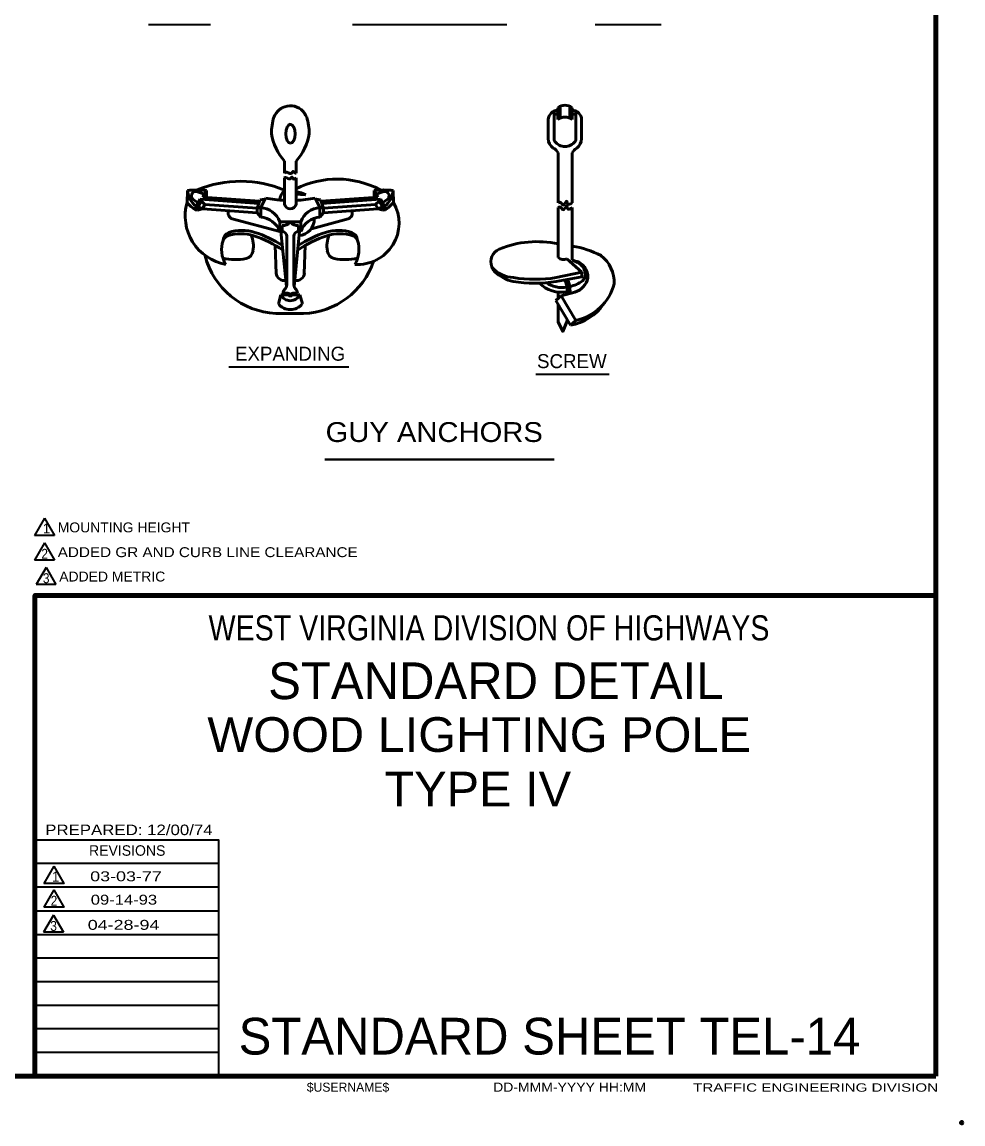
# Model space of a CAD drawing. Extents: x -34 to 821, y -14 to 530.
# Drawn here: x 593.8 to 821.5, y -13.8 to 252.8 of the extents above; entities that cross this region are included whole.
import ezdxf
from ezdxf.enums import TextEntityAlignment as Align

# ---------------------------------------------------------------- set-up
doc = ezdxf.new("R2010")
doc.units = 0
doc.header["$LTSCALE"] = 1.2
doc.header["$PDMODE"] = 32
doc.header["$PDSIZE"] = 0.6
doc.layers.add('1', color=7, linetype='Continuous', lineweight=53)
doc.layers.add('61', color=7, linetype='Continuous', lineweight=35)

msp = doc.modelspace()

# ---------------------------------------------------------------- linework, layer by layer
at = {"layer": '1', "lineweight": 158}
for q in [(814.88, 523.876), (814.88, 114.076), (23.28, -2.224)]:
    msp.add_line((814.88, -2.224), q, dxfattribs=at)
at = {"layer": '1', "lineweight": 13}
for p, q in [((814.88, -2.224), (814.88, 523.876)), ((723.474, 185.953), (723.474, 185.737))]:
    msp.add_line(p, q, dxfattribs=at)
at = {"layer": '1', "lineweight": 35}
for p, q in [((624.356, 252.214), (639.38, 252.214)), ((673.772, 252.214), (711.091, 252.214)), ((732.5, 252.214), (748.436, 252.214)), ((643.829, 169.376), (672.858, 169.376)), ((718.089, 167.576), (735.866, 167.576)), ((599.197, 132.752), (596.797, 128.595)), ((599.197, 132.752), (601.597, 128.595)), ((601.597, 128.595), (596.797, 128.595)), ((599.197, 126.756), (596.797, 122.599)), ((599.197, 126.756), (601.597, 122.599)), ((601.597, 122.599), (596.797, 122.599)), ((599.566, 120.857), (597.166, 116.7)), ((599.566, 120.857), (601.966, 116.7)), ((601.966, 116.7), (597.166, 116.7)), ((641.38, 49.176), (596.88, 49.176)), ((601.475, 48.54), (599.075, 44.383)), ((641.38, 43.476), (596.88, 43.476)), ((601.456, 42.798), (599.056, 38.641)), ((641.38, 37.676), (596.88, 37.676)), ((601.359, 36.71), (598.959, 32.553)), ((601.359, 36.71), (603.759, 32.553)), ((603.759, 32.553), (598.959, 32.553)), ((641.38, 31.976), (596.88, 31.976)), ((641.38, 26.276), (596.88, 26.276)), ((641.38, 20.576), (596.88, 20.576)), ((641.38, 14.876), (596.88, 14.876)), ((641.38, 9.176), (596.88, 9.176)), ((641.38, 3.476), (596.88, 3.476))]:
    msp.add_line(p, q, dxfattribs=at)
at = {"layer": '1'}
for p, q in [((723.426, 232.081), (723.426, 229.201)), ((724.002, 232.417), (724.002, 229.537)), ((726.306, 232.417), (726.306, 229.537)), ((726.882, 232.081), (726.882, 229.201)), ((722.514, 231.289), (722.514, 224.497)), ((727.818, 231.289), (727.818, 224.473)), ((721.122, 229.201), (721.122, 224.593)), ((729.186, 229.201), (729.186, 224.593)), ((657.282, 219.145), (657.282, 216.265)), ((660.09, 219.145), (660.09, 216.265)), ((723.474, 221.161), (723.474, 209.065)), ((726.93, 221.161), (726.93, 209.065)), ((657.282, 215.113), (657.282, 208.777)), ((660.09, 215.113), (660.09, 208.777)), ((633.81, 212.065), (633.714, 209.185)), ((637.938, 211.153), (636.018, 211.825)), ((638.418, 212.065), (637.53, 210.433)), ((637.938, 211.153), (637.938, 210.409)), ((638.418, 212.065), (638.418, 210.361)), ((678.954, 212.065), (679.842, 210.457)), ((678.954, 212.065), (678.954, 210.385)), ((679.434, 211.153), (681.354, 211.825)), ((679.434, 211.153), (679.434, 210.409)), ((683.562, 212.065), (683.658, 209.185)), ((636.378, 209.041), (635.202, 209.881)), ((636.882, 209.953), (635.898, 208.153)), ((635.898, 208.153), (636.474, 208.177)), ((637.458, 207.577), (636.474, 208.177)), ((651.042, 208.945), (636.882, 209.953)), ((637.194, 209.473), (637.194, 209.929)), ((638.034, 208.681), (637.194, 209.473)), ((638.034, 208.681), (637.458, 207.577)), ((651.234, 209.473), (637.53, 210.433)), ((650.658, 207.793), (638.034, 208.681)), ((652.53, 209.929), (651.402, 209.761)), ((652.674, 210.217), (651.522, 207.913)), ((664.698, 210.217), (665.85, 207.913)), ((664.842, 209.929), (665.97, 209.761)), ((666.138, 209.497), (679.842, 210.457)), ((666.33, 208.945), (680.49, 209.953)), ((666.714, 207.793), (679.338, 208.681)), ((679.338, 208.681), (680.178, 209.473)), ((679.338, 208.681), (679.914, 207.577)), ((679.914, 207.577), (680.898, 208.177)), ((680.178, 209.473), (680.178, 209.929)), ((680.49, 209.953), (681.474, 208.153)), ((681.474, 208.153), (680.898, 208.177)), ((680.994, 209.041), (682.17, 209.881)), ((637.458, 207.577), (636.33, 207.313)), ((650.658, 206.641), (637.458, 207.577)), ((651.522, 207.913), (650.658, 207.793)), ((651.522, 207.913), (651.522, 205.609)), ((665.85, 207.913), (665.85, 205.609)), ((665.85, 207.913), (666.714, 207.793)), ((666.714, 206.641), (679.914, 207.577)), ((679.914, 207.577), (681.042, 207.313)), ((723.474, 207.913), (723.474, 195.817)), ((726.93, 207.913), (726.93, 195.217)), ((656.13, 202.105), (644.658, 205.201)), ((656.13, 204.457), (661.242, 204.457)), ((656.13, 204.457), (656.13, 202.105)), ((656.706, 203.593), (656.706, 202.153)), ((660.666, 203.593), (660.666, 202.153)), ((661.242, 204.457), (661.242, 202.153)), ((663.786, 202.801), (672.69, 205.201)), ((656.13, 202.153), (656.706, 202.153)), ((656.418, 202.153), (657.762, 188.833)), ((657.858, 201.001), (657.858, 189.481)), ((659.514, 201.001), (659.514, 189.481)), ((660.954, 202.153), (659.61, 188.833)), ((660.666, 202.153), (661.242, 202.153)), ((655.29, 191.881), (655.05, 198.793)), ((662.082, 191.881), (662.322, 198.793)), ((725.61, 195.553), (729.258, 192.289)), ((729.258, 192.289), (723.042, 190.969)), ((725.85, 190.537), (726.354, 188.881)), ((656.394, 186.817), (655.794, 184.609)), ((656.394, 186.817), (658.122, 186.817)), ((656.946, 187.201), (658.098, 187.201)), ((660.402, 187.201), (659.25, 187.201)), ((661.002, 186.817), (659.274, 186.817)), ((661.002, 186.817), (661.602, 184.609)), ((723.474, 187.489), (723.474, 185.881)), ((727.554, 187.441), (724.218, 186.553)), ((726.354, 188.881), (726.45, 187.153)), ((724.218, 186.553), (722.922, 185.401)), ((722.922, 185.401), (726.498, 179.473)), ((724.218, 186.553), (727.77, 180.625)), ((655.17, 182.281), (661.914, 182.281)), ((727.77, 180.625), (726.498, 179.473))]:
    msp.add_line(p, q, dxfattribs=at)
at = {"layer": '1', "lineweight": 40}
msp.add_line((667.007, 146.921), (722.513, 146.921), dxfattribs=at)
at = {"layer": '1'}
for points in [[(635.898, 208.153), (635.754, 207.409), (636.33, 207.313)], [(637.194, 209.473), (636.474, 208.177), (636.33, 207.313)], [(651.402, 209.761), (650.658, 207.793), (650.658, 206.641), (651.522, 205.609)], [(665.97, 209.761), (666.714, 207.793), (666.714, 206.641), (665.85, 205.609)], [(680.178, 209.473), (680.898, 208.177), (681.042, 207.313)], [(681.474, 208.153), (681.618, 207.409), (681.042, 207.313)], [(729.258, 192.289), (729.258, 191.137), (723.018, 190.033)], [(725.178, 190.321), (725.682, 188.665), (725.778, 186.937)], [(723.474, 184.489), (723.474, 180.265), (724.626, 177.961), (725.778, 180.649)]]:
    msp.add_lwpolyline(points, dxfattribs=at)
at = {"layer": '1', "lineweight": 158}
msp.add_lwpolyline([(596.88, -2.224), (596.88, 114.076), (814.88, 114.076)], dxfattribs=at)
at = {"layer": '1', "lineweight": 35}
for points in [[(641.38, -2.224), (641.38, 54.876), (596.88, 54.876)], [(601.475, 48.54), (603.875, 44.383), (599.075, 44.383)], [(601.456, 42.798), (603.856, 38.641), (599.056, 38.641)]]:
    msp.add_lwpolyline(points, dxfattribs=at)
at = {"layer": '1'}
for centre, radius, start, end in [((658.553, 228.245), 4.221, 114.18463, 126.44768), ((658.718, 228.342), 4.205, 51.67793, 116.77606), ((725.163, 229.847), 2.826, 52.29201, 127.70799), ((667.677, 225.854), 13.56, 163.03649, 180.34718), ((659.741, 227.532), 5.526, 131.96494, 155.64508), ((657.631, 227.532), 5.526, 24.35492, 48.03506), ((649.695, 225.854), 13.56, 359.65283, 16.96351), ((723.537, 229.099), 2.409, 92.45547, 177.54453), ((723.396, 229.361), 1.282, 88.28293, 133.52461), ((725.163, 226.967), 2.826, 52.29201, 127.70799), ((726.787, 229.099), 2.409, 2.45547, 87.54453), ((726.928, 229.361), 1.282, 46.47539, 91.71707), ((667.395, 228.053), 13.473, 189.74744, 221.3725), ((649.976, 228.053), 13.473, 318.6275, 350.25256), ((723.965, 224.616), 2.835, 180.43177, 234.62969), ((723.371, 224.475), 0.859, 179.14798, 220.24311), ((726.949, 224.47), 0.859, 319.75689, 0.85202), ((726.359, 224.616), 2.835, 305.37031, 359.56823), ((721.322, 220.15), 2.375, 24.94304, 65.05696), ((725.162, 225.758), 3.06, 216.91814, 322.98043), ((729.015, 220.292), 2.254, 116.76572, 157.56298), ((646.647, 186.688), 27.599, 67.32753, 112.30219), ((669.989, 192.427), 22.38, 62.24214, 116.49544), ((639.464, 212.566), 5.674, 185.18056, 230.94579), ((636.118, 190.105), 22.07, 84.00757, 95.99243), ((635.815, 210.763), 1.075, 78.96142, 235.46809), ((659.26, 209.463), 3.174, 128.46984, 175.06692), ((656.113, 197.66), 14.729, 64.65247, 74.23543), ((660.567, 199.914), 11.211, 80.48984, 92.29918), ((681.254, 190.105), 22.07, 84.00757, 95.99243), ((681.523, 210.749), 1.083, 306.45493, 99.11556), ((677.907, 212.566), 5.674, 309.05421, 354.81944), ((645.157, 205.897), 11.904, 164.01359, 259.79898), ((639.179, 213.429), 6.926, 217.89069, 240.44911), ((659.957, 249.745), 40.189, 259.56289, 266.18708), ((658.686, 209.062), 1.429, 191.39485, 348.60515), ((657.414, 249.745), 40.189, 273.81292, 280.43711), ((674.993, 204.168), 10.008, 266.16365, 30.02378), ((678.193, 213.429), 6.926, 299.55089, 322.10931), ((645.125, 206.595), 1.482, 158.99371, 251.37679), ((651.145, 202.61), 5.319, 20.35078, 85.90942), ((651.145, 200.306), 5.319, 20.35078, 85.90942), ((666.226, 202.61), 5.319, 94.09058, 159.64922), ((666.226, 200.306), 5.319, 94.09058, 159.64922), ((672.214, 206.595), 1.482, 288.62321, 21.00629), ((656.963, 205.91), 2.327, 263.73433, 317.75599), ((660.409, 205.91), 2.327, 222.24401, 276.26567), ((660.53, 205.098), 3.962, 273.98395, 2.60406), ((649.253, 197.804), 7.185, 162.29086, 210.27517), ((644.828, 199.711), 2.435, 115.12547, 173.42944), ((644.616, 198.872), 2.474, 116.11742, 153.15373), ((646.695, 191.239), 10.351, 72.17801, 107.82199), ((646.962, 191.064), 11.304, 73.72458, 106.27542), ((643.764, 198.619), 6.01, 348.82631, 26.25382), ((641.469, 175.233), 27.189, 55.49077, 72.01683), ((641.469, 175.233), 28.053, 56.96697, 72.01675), ((656.556, 200.852), 1.313, 6.66371, 83.33629), ((660.815, 200.852), 1.313, 96.66371, 173.33629), ((675.903, 175.233), 27.189, 107.98317, 124.50923), ((675.903, 175.233), 28.053, 107.98325, 123.03303), ((670.41, 191.064), 11.304, 73.72458, 106.27542), ((670.676, 191.239), 10.351, 72.17801, 107.82199), ((673.546, 198.619), 6.01, 153.74618, 191.17369), ((672.544, 199.711), 2.435, 6.57056, 64.87453), ((672.755, 198.872), 2.474, 26.84627, 63.88258), ((668.118, 197.804), 7.185, 329.72483, 17.70914), ((647.557, 197.666), 2.114, 282.14771, 354.26068), ((669.753, 197.666), 2.114, 185.73932, 257.85229), ((710.554, 194.786), 3.334, 112.56326, 201.22601), ((718.358, 175.972), 23.702, 77.48956, 112.53539), ((722.98, 174.809), 24.114, 63.12438, 80.5666), ((656.147, 200.912), 18.657, 194.44102, 266.97322), ((645.372, 207.745), 12.427, 256.06592, 282.21618), ((661.163, 200.912), 18.657, 272.30306, 341.28411), ((671.938, 207.745), 12.427, 257.78382, 283.93408), ((724.722, 197.189), 1.86, 227.92906, 298.55891), ((724.57, 188.608), 7.023, 47.97836, 70.34854), ((727.203, 192.037), 2.996, 60.03867, 86.11071), ((728.951, 189.861), 8.108, 357.06801, 53.01462), ((657.247, 192.242), 1.991, 186.64556, 280.42286), ((660.125, 192.242), 1.991, 259.57714, 353.35444), ((766.452, 221.176), 65.141, 205.06602, 205.618), ((713.129, 198.528), 7.58, 221.76894, 266.63849), ((710.672, 194.66), 3.382, 205.89722, 222.96556), ((713.914, 198.182), 8.163, 225.54603, 243.17205), ((726.452, 190.962), 4.304, 37.20204, 58.52155), ((727.015, 191.735), 3.076, 345.49101, 42.81927), ((726.414, 191), 4.312, 358.21611, 36.4931), ((655.419, 189.573), 2.443, 329.93461, 357.90459), ((661.952, 189.573), 2.443, 182.09541, 210.06539), ((713.669, 196.645), 6.697, 239.10628, 261.18034), ((717.826, 223.468), 33.84, 261.18821, 278.81179), ((717.868, 224.403), 33.84, 261.18821, 278.81179), ((724.488, 195.538), 8.122, 226.52134, 278.94966), ((724.488, 195.538), 6.97, 235.85618, 279.93742), ((724.469, 196.831), 8.25, 282.93456, 306.7285), ((726.112, 191.962), 4.74, 287.7219, 346.62294), ((725.306, 192.509), 12.135, 281.74498, 345.38421), ((727.87, 192.042), 2.381, 310.05064, 333.08561), ((658.693, 187.951), 2.563, 205.98923, 334.01077), ((658.4, 187.196), 1.442, 126.91323, 179.95667), ((657.98, 186.491), 0.718, 10.44919, 79.5508), ((657.987, 186.121), 0.718, 10.44919, 79.5508), ((659.392, 186.491), 0.718, 100.4492, 169.55081), ((659.399, 186.121), 0.718, 100.4492, 169.55081), ((658.972, 187.196), 1.442, 0.04333, 53.08677), ((658.693, 186.959), 3.737, 219.10281, 320.89719), ((724.448, 191.494), 12.195, 279.6497, 325.48694)]:
    msp.add_arc(centre, radius, start, end, dxfattribs=at)
msp.add_ellipse((658.725, 225.772), major_axis=(0, -2.304), ratio=0.5, dxfattribs=at)
for points in [[(657.282, 216.265), (657.714, 216.505), (658.194, 216.361), (658.986, 216.241), (659.37, 216.697), (659.826, 216.265), (660.09, 216.265)], [(657.282, 215.113), (657.522, 215.185), (658.65, 214.873), (659.13, 215.305), (659.394, 214.873), (660.09, 215.113)], [(723.474, 209.065), (724.098, 209.185), (724.674, 208.537), (725.61, 209.449), (725.802, 208.801), (726.93, 209.065)], [(723.474, 207.913), (724.098, 208.033), (724.674, 207.385), (725.61, 208.297), (725.802, 207.649), (726.93, 207.913)]]:
    msp.add_spline(points, degree=3, dxfattribs=at)
msp.add_point((821.18, -13.524), dxfattribs=at)
at = {"layer": '61', "lineweight": 53}
for q in [(662.18, -2.224), (662.18, -2.224), (662.18, -2.224), (662.48, -2.224), (662.48, -2.224)]:
    msp.add_line((814.88, -2.224), q, dxfattribs=at)

# ---------------------------------------------------------------- texts
at = {"layer": '1'}
for s, height, p in [('EXPANDING', 3.387, (658.639, 170.864)), ('SCREW', 3.387, (726.824, 169.064)), ('STANDARD DETAIL', 8.881, (708.43, 88.976))]:
    msp.add_text(s, height=height, dxfattribs=at).set_placement(p, align=Align.CENTER)
for s, height, width, p in [('GUY ANCHORS', 4.8, 1.1, (667.232, 151.198)), ('MOUNTING HEIGHT', 2.4, 1.05, (602.402, 129.33)), ('2', 2.4, 0.9, (598.433, 122.936)), ('ADDED GR AND CURB LINE CLEARANCE', 2.4, 1.15, (602.402, 123.334)), ('3', 2.4, 0.9, (598.802, 117.037)), ('ADDED METRIC', 2.4, 1.05, (602.77, 117.436)), ('PREPARED: 12/00/74', 2.537, 1.2, (599.38, 56.076)), ('2', 2.4, 0.9, (600.692, 38.978)), ('3', 2.4, 0.9, (600.595, 32.89)), ('DD-MMM-YYYY HH:MM', 2.2, 1.15, (707.779, -6.024)), ('TRAFFIC ENGINEERING DIVISION', 2.031, 1.35, (756.18, -6.024))]:
    msp.add_text(s, height=height, dxfattribs=dict(at, width=width)).set_placement(p)
for s, height, p in [('1', 2.4, (598.797, 129.084)), ('REVISIONS', 2.537, (609.98, 51.076)), ('1', 2.4, (601.007, 44.826)), ('STANDARD SHEET TEL-14', 8.881, (646.18, 2.976)), ('$USERNAME$', 2.2, (662.68, -6.024))]:
    msp.add_text(s, height=height, dxfattribs=at).set_placement(p)
for s, height, width, p in [('WEST VIRGINIA DIVISION OF HIGHWAYS', 6.089, 0.85, (706.779, 103.176)), ('WOOD LIGHTING POLE', 8.391, 1.05, (704.385, 76.21)), ('TYPE IV', 8.391, 1.05, (704.055, 63.019)), ('03-03-77', 2.4, 1.35, (618.924, 44.907)), ('09-14-93', 2.4, 1.25, (618.426, 39.239)), ('04-28-94', 2.4, 1.35, (618.338, 33.151))]:
    msp.add_text(s, height=height, dxfattribs=dict(at, width=width)).set_placement(p, align=Align.CENTER)

doc.saveas('drawing.dxf')
